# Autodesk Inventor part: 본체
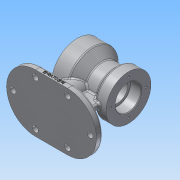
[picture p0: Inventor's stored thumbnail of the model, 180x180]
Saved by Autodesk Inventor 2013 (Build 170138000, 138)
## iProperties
Created: 2020-01
Part Number: 본체
Material: 알루미늄 6061
Document SubType Name: Modeling
Designer: Administrator
Density: 2.71 g/cm^3
Mass: 933.557 g
Surface Area: 655.825 cm^2
Volume: 344.486 cm^3
Author: Administrator
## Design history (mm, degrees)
sketch "스케치1"
  geometry: L1 (-40, 0)-(40, 0); L2 (-40, 40)-(-40, 0); L3 (-40, 40)-(-16, 40); L4 (-16, 40)-(-1.103, 27.5); L5 (-1.103, 27.5)-(17.707, 27.5); L6 (17.707, 27.5)-(24, 35); L7 (24, 35)-(40, 35); L8 (40, 35)-(40, 0); 2 further points
  constraints: 16 end point, 4 perpendicular, 2 coincident, 2 midpoint, 2 parallel, 1 horizontal
  dimensions: "d0" = 80 distance between parallel lines of L8 L2; "d2" = 55 diameter of L5 L1; "d4" = 24 distance of L2.start L3.end; "d5" = 80 diameter of L3 L1; "d6" = 40 deg angle of L4 L5; "d8" = 70 diameter of L7 L1; "d10" = 16 distance of L6.end L7.end
revolve "회전1" sketch "스케치1" stored, may be unused: angle "d11" = 90 deg
sketch "스케치2"
  geometry: C1 r 35 at (0, 0) reference; C2 r 20 at (0, 0)
  constraints: 1 centre point, 1 coincident
  dimensions: "d12" = 40 diameter of C2
extrude "돌출1" cut sketch "스케치2" distance "d13" = 17; taper "d14" = 0 deg
sketch "스케치3"
  geometry: C1 r 20 at (0, 0) reference; C2 r 16 at (0, 0)
  constraints: 1 centre point, 1 coincident
  dimensions: "d15" = 32 diameter of C2
extrude "돌출2" cut sketch "스케치3" stored distance "d16" = 17; taper "d17" = 0 deg
sketch "스케치4"
  geometry: C1 r 16 at (0, 0) reference; C2 r 40 at (0, 0) reference; C3 r 26 at (0, 0)
  constraints: 1 centre point, 1 coincident
  dimensions: "d18" = 52 diameter of C3
extrude "돌출3" cut sketch "스케치4" distance "d19" = 20; taper "d20" = 0 deg
sketch "스케치5"
  geometry: C1 r 26 at (0, 0) reference; 1 further point
  constraints: 1 vertical alignment
  dimensions: "d21" = 33 distance of point (0, 33) C1.centre
hole "구멍1" sketch "스케치5" at (0, 33) diameter "d22" = 3.242; stored, may be unused: countersink angle "d26" = 90 deg, drill point angle "d28" = 118 deg; dims "d23" = 9, "d24" = 4, "d25" = 2, "d27" = 11
sketch "스케치6"
  geometry: C1 r 20 at (0, 0) reference; 1 further point
  constraints: 1 vertical alignment
  dimensions: "d32" = 27.5 distance of C1.centre point (0, 27.5)
hole "구멍2" sketch "스케치6" at (0, 27.5) diameter "d33" = 3.242; stored, may be unused: countersink angle "d37" = 90 deg, drill point angle "d39" = 118 deg; dims "d34" = 9, "d35" = 4, "d36" = 2, "d38" = 11
sketch "스케치7"
  geometry: L1 (-70, -45)-(-80, -45); L2 (-80, -45)-(-80, 45); L3 (-80, 45)-(-70, 45); L4 (-70, 45)-(-70, -45); 2 further points
  constraints: 8 end point, 2 parallel, 1 horizontal, 1 horizontal alignment, 1 midpoint, 1 perpendicular
  dimensions: "d43" = 90 distance of L1.end L2.end; "d45" = 10 distance of L2.end L3.end; "d46" = 80 distance from line of L2 point (0, 0)
extrude "돌출4" join sketch "스케치7" stored distance "d47" = 140; taper "d48" = 0 deg
fillet "모깎기1" dims "d49" = 45
sketch "스케치8"
  geometry: L1 (0, 0)-(50, 0) reference; L2 (50, -90)-(0, -90) reference; L3 (0, -10)-(50, -10); L4 (50, -80)-(0, -80); L5 (-0.767, -45)-(-45, -45); L6 (20, -40)-(55, -40); L7 (55, -40)-(55, -50); L8 (55, -50)-(20, -50); L9 (20, -50)-(20, -40); C1 r 16 at (13, -45); C2 r 4.5 at (0, -10); C3 r 4.5 at (-35, -45); A1 r 45 centre (50, -45) between (50, -90) and (50, 0) reference; A2 r 45 centre (0, -45) between (0, 0) and (0, -90) reference; A3 r 45 centre (0, -45) between (0, 0) and (0, -90) reference; A4 r 35 centre (0, -45) between (0, -10) and (0, -80); A5 r 35 centre (50, -45) between (50, -80) and (50, -10); 5 further points
  constraints: 14 end point, 6 point on circle, 5 centre point, 4 coincident, 3 parallel, 2 horizontal alignment, 1 horizontal, 1 midpoint, 1 perpendicular, 1 point on line, 2 other
  dimensions: "d50" = 10 distance between parallel lines of L3 L1; "d51" = 10 radial gap between concentric circles of A2 A4; "d52" = 58 distance of point (13, -45) L5.end; "d53" = 32 diameter of C1; "d54" = 9 diameter of C2; "d55" = 9 diameter of C3; "d58" = 30 distance from line of L7 point (25, -45); "d59" = 10 distance of L6.end L7.end; "d60" = 35 distance between parallel lines of L7 L9
extrude "돌출5" cut sketch "스케치8" distance "d56" = 10; taper "d57" = 0 deg
extrude "돌출6" join sketch "스케치8" stored distance "d61" = 10; taper "d62" = 0 deg
fillet "모깎기2" dims "d63" = 0.3
chamfer "모따기1" distance "d64" = 1; stored, may be unused: second distance "d65" = 2, angle "d66" = 45 deg
fillet "모깎기3" dims "d67" = 3
fillet "모깎기4" dims "d68" = 3
fillet "모깎기5" dims "d69" = 3
sketch "스케치10"
  geometry: L1 (50, 0)-(0, 0) reference; L2 (-45, 0)-(-45, 7) reference; 2 further points
  constraints: 1 other
  dimensions: "d74" = 4 distance from line of L1 point (25, 4); "d75" = 70 distance from line of point (25, 4) L2
feature "엠보싱2" sketch "스케치10" dims "d15" = 32, "d76" = 0.5, "d77" = 0
node "솔리드1"
pattern_circular "원형 패턴1" dims angle "d30" = 360 deg
pattern_circular "원형 패턴2" dims angle "d41" = 360 deg
mirror "대칭1"
mirror "대칭2"
